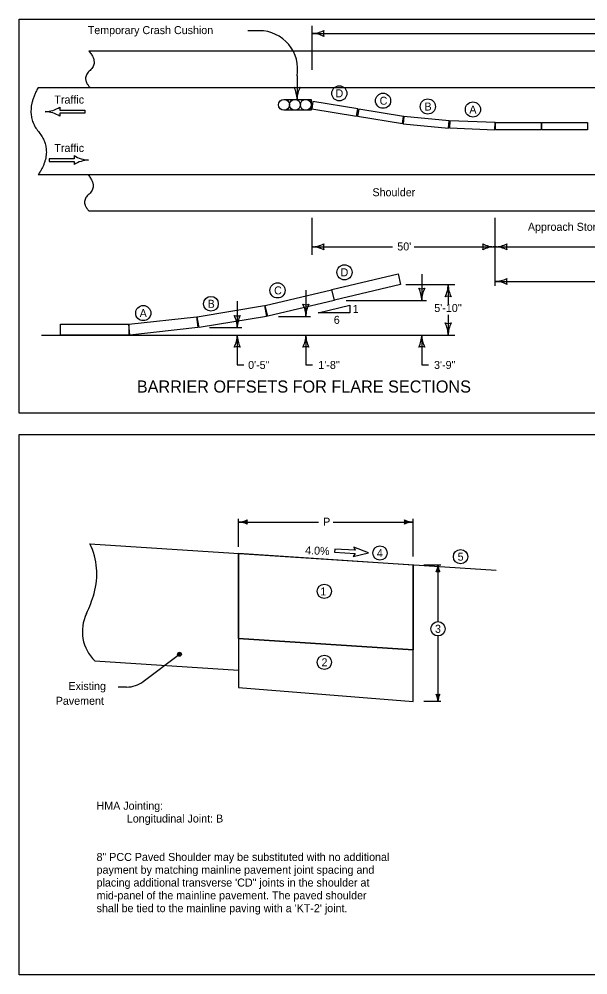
# Model space of a CAD drawing. Extents: x 8045 to 81668, y 6217 to 16762.
# Drawn here: x 13482 to 14421, y 10929 to 12506 of the extents above; entities that cross this region are included whole.
import ezdxf

# ---------------------------------------------------------------- set-up
doc = ezdxf.new("R2010")
doc.units = 0
doc.layers.add('dsnStdLineWork', color=7, linetype='Continuous')

msp = doc.modelspace()

# ---------------------------------------------------------------- linework, layer by layer
at = {"layer": 'dsnStdLineWork'}
for p, q in [((13482.4, 12505.5), (16587.4, 12505.5)), ((13482.4, 11855.5), (13482.4, 12505.5)), ((13965.3, 12494.7), (13965.3, 12422.1)), ((13878.8, 12486.4), (13860.1, 12486.4)), ((13965.3, 12481.9), (14898.2, 12481.9)), ((13597.7, 12453), (14726.2, 12453)), ((13941.1, 12411.7), (13941.1, 12373.1)), ((13514.1, 12393), (14756.2, 12393)), ((13919.5, 12373.1), (13964.5, 12373.1)), ((13964.5, 12373.1), (13964.5, 12355.1)), ((13525.6, 12352.8), (13525.6, 12352.8)), ((13549.5, 12360.3), (13549.5, 12355.1)), ((13549.5, 12355.1), (13590.8, 12355.1)), ((13590.8, 12350.6), (13549.5, 12350.6)), ((13549.5, 12350.6), (13549.5, 12345.3)), ((13590.8, 12355.1), (13590.8, 12350.6)), ((13964.5, 12355.1), (13919.5, 12355.1)), ((13963.3, 12360.8), (13964.6, 12360.5)), ((13965, 12357.1), (13965, 12357.1)), ((13573.1, 12275.2), (13531.9, 12275.2)), ((13531.9, 12275.2), (13531.9, 12270.7)), ((13531.9, 12270.7), (13573.1, 12270.7)), ((13573.1, 12280.5), (13573.1, 12275.2)), ((13573.1, 12270.7), (13573.1, 12265.5)), ((13597.1, 12273), (13597.1, 12273)), ((13514.1, 12249), (14756.2, 12249)), ((13597.7, 12189), (14726.2, 12189)), ((13965.3, 12177.7), (13965.3, 12116.5)), ((14267.5, 12177.7), (14267.5, 12065.3)), ((13965.3, 12129.9), (14098.8, 12129.9)), ((14134.1, 12129.9), (14267.5, 12129.9)), ((14267.5, 12129.9), (14493.6, 12129.9)), ((14146.8, 12085), (14146.8, 12041.6)), ((14120.8, 12067.5), (14201.2, 12067.5)), ((14190.4, 12067.5), (14190.4, 12034.1)), ((14267.5, 12072.8), (14858.3, 12072.8)), ((13955.6, 12058.6), (13955.6, 12015.1)), ((13842.4, 12040.1), (13842.4, 11996.6)), ((13975.7, 12021.2), (14028.3, 12033.6)), ((14021.9, 12041.6), (14154.5, 12041.6)), ((14028.3, 12033.6), (14028.3, 12021.2)), ((13910.6, 12015.1), (13963.4, 12015.1)), ((14028.3, 12021.2), (13975.7, 12021.2)), ((14190.4, 12017.7), (14190.4, 11984.3)), ((13519.4, 11984.3), (14201.2, 11984.3)), ((13796.4, 11996.6), (13850.2, 11996.6)), ((13842.4, 11984.3), (13842.4, 11957.3)), ((13955.6, 11984.3), (13955.6, 11935)), ((14146.8, 11984.3), (14146.8, 11935)), ((13842.4, 11957.3), (13842.4, 11935)), ((13842.4, 11935), (13853.5, 11935)), ((13955.6, 11935), (13966.8, 11935)), ((14146.8, 11935), (14157.9, 11935)), ((16587.4, 11855.5), (13482.4, 11855.5)), ((13844.4, 11635.1), (13844.4, 11681.4)), ((13844.4, 11675.8), (13858.3, 11675.8)), ((13844.4, 11675.8), (13976.7, 11675.8)), ((14000.6, 11675.8), (14132.9, 11675.8)), ((14132.9, 11675.8), (14119.1, 11675.8)), ((14132.9, 11619), (14132.9, 11681.4)), ((13599, 11640.1), (14269.4, 11596.7)), ((14150.2, 11605.5), (14178.2, 11605.5)), ((14173.6, 11605.5), (14173.6, 11594.1)), ((14173.6, 11605.5), (14173.6, 11511.5)), ((13844.4, 11483.8), (14132.9, 11465.1)), ((14173.6, 11488), (14173.6, 11379.9)), ((13687.3, 11413), (13747.3, 11457.9)), ((13607.2, 11446.7), (13844.4, 11431.4)), ((13659.8, 11403.6), (13645.8, 11403.6)), ((14173.6, 11379.9), (14173.6, 11391.4)), ((14178.2, 11379.9), (14150.2, 11379.9))]:
    msp.add_line(p, q, dxfattribs=at)
for points in [[(14041.3, 12357.5), (13967.3, 12369.6), (13965.3, 12357.8), (14039.4, 12345.6)], [(14116.8, 12345.1), (14042.8, 12357.2), (14040.8, 12345.4), (14114.9, 12333.3)], [(14192.2, 12337.9), (14117.5, 12345), (14116.4, 12333), (14191.1, 12325.9)], [(14268, 12335), (14193, 12337.9), (14192.6, 12326), (14267.5, 12323)], [(14268.7, 12335), (14343.7, 12335), (14343.7, 12323), (14268.7, 12323)], [(14345.2, 12335), (14420.2, 12335), (14420.2, 12323), (14345.2, 12323)], [(13998.4, 12059.2), (14107.9, 12085.1), (14112, 12067.6), (14002.6, 12041.7)], [(13888.6, 12033.2), (13998.1, 12059.1), (14002.2, 12041.6), (13892.7, 12015.7)], [(13776.5, 12014.5), (13887.5, 12032.9), (13890.5, 12015.1), (13779.5, 11996.7)], [(13550.9, 12002.4), (13663.4, 12002.3), (13663.4, 11984.3), (13550.9, 11984.4)], [(13663.4, 12002.1), (13775.3, 12014.5), (13777.2, 11996.6), (13665.4, 11984.3)], [(13482.4, 11820.1), (15033.1, 11820.1), (15033.1, 10928.8), (13482.4, 10928.8)], [(13844.4, 11624.4), (14132.9, 11605.5), (14132.9, 11465.1), (13844.4, 11483.8)], [(14033.7, 11619.1), (14058.7, 11625.3), (14034.6, 11634.3), (14037.2, 11629.2), (14003.4, 11631.3), (14003, 11626.2), (14036.9, 11624)]]:
    msp.add_lwpolyline(points, close=True, dxfattribs=at)
for points in [[(13858, 11673.2), (13857.5, 11675.8), (13858, 11678.4), (13854.9, 11676.9), (13850, 11675.8), (13855.3, 11674.5), (13857.6, 11673.5), (13857, 11675.8), (13857.2, 11677.4), (13855.2, 11676.5), (13852.5, 11675.8), (13855.4, 11674.9), (13856.9, 11674.4), (13856.6, 11676.6), (13854.6, 11675.8), (13856.2, 11675.3), (13856.2, 11676), (13855.4, 11675.8)], [(14119.4, 11678.3), (14119.9, 11675.8), (14119.3, 11673.2), (14122.4, 11674.6), (14127.4, 11675.8), (14122.1, 11677), (14119.8, 11678), (14120.4, 11675.8), (14120.1, 11674.1), (14122.2, 11675.1), (14124.9, 11675.8), (14122, 11676.6), (14120.5, 11677.1), (14120.8, 11674.9), (14122.8, 11675.8), (14121.2, 11676.3), (14121.2, 11675.5), (14121.9, 11675.7)], [(13844.4, 11624.4), (13844.4, 11402.6), (14132.9, 11379.9), (14132.9, 11605.5)], [(14171.5, 11594.3), (14173.6, 11594.7), (14175.7, 11594.3), (14174.5, 11596.8), (14173.6, 11600.9), (14172.6, 11596.5), (14171.7, 11594.7), (14173.6, 11595.1), (14175, 11595), (14174.2, 11596.6), (14173.6, 11598.9), (14172.9, 11596.5), (14172.5, 11595.2), (14174.3, 11595.5), (14173.6, 11597.1), (14173.2, 11595.8), (14173.8, 11595.8), (14173.6, 11596.4)], [(13749.3, 11459.6), (13748.2, 11460), (13746.7, 11460.8), (13745.3, 11459.8), (13744.4, 11458.6), (13744.2, 11456.9), (13745.4, 11455.9), (13746.7, 11454.9), (13748.2, 11455.3), (13749.3, 11456.1), (13749.9, 11458.1), (13749.2, 11459.1), (13747.7, 11460), (13746, 11460.2), (13744.9, 11459), (13744.8, 11457.4), (13745.7, 11456.2), (13747.1, 11455.3), (13748, 11455.8), (13749, 11456.3), (13749.4, 11457.9), (13748.5, 11458.7), (13747.4, 11459.5), (13746.1, 11459.7), (13745.5, 11458.3), (13745.7, 11457), (13746.6, 11456), (13747.4, 11456.3), (13748.3, 11456.6), (13748.6, 11457.8), (13748.1, 11458.7), (13747.1, 11459), (13746.3, 11458.4), (13746.1, 11457.5), (13746.6, 11456.7), (13747.2, 11456.6), (13747.8, 11456.8), (13748, 11457.7), (13747.7, 11458.3), (13747, 11458.5), (13746.6, 11458), (13746.7, 11457.4), (13747.2, 11457), (13747.5, 11457.3), (13747.3, 11457.9)], [(14175.7, 11391.1), (14173.6, 11390.7), (14171.4, 11391.1), (14172.7, 11388.6), (14173.6, 11384.5), (14174.6, 11388.9), (14175.4, 11390.8), (14173.6, 11390.3), (14172.2, 11390.5), (14173, 11388.8), (14173.6, 11386.6), (14174.3, 11388.9), (14174.7, 11390.2), (14172.9, 11390), (14173.6, 11388.3), (14174, 11389.6), (14173.4, 11389.6), (14173.6, 11389)]]:
    msp.add_lwpolyline(points, dxfattribs=at)
for centre, radius in [((14010.8, 12383.1), 12.5), ((14083, 12370.9), 12.5), ((13919.5, 12364.1), 9), ((13919.5, 12364.1), 9), ((13937.5, 12364.1), 9), ((13937.5, 12364.1), 9), ((13955.5, 12364.1), 9), ((13955.5, 12364.1), 9), ((14156.8, 12361.3), 12.5), ((14231.3, 12356.4), 12.5), ((14019.3, 12087.8), 12.5), ((13908.9, 12058), 12.5), ((13798.9, 12035.9), 12.2), ((13687.3, 12020.6), 12.5), ((14077.9, 11624.7), 11.8), ((14210.9, 11618.7), 11.8), ((13986, 11561.6), 11.8), ((14173.6, 11499.7), 11.8), ((13747.1, 11457.7), 3.15), ((13986.1, 11444.4), 11.8)]:
    msp.add_circle(centre, radius, dxfattribs=at)
for centre, radius, start, end in [((13878.8, 12423.1), 63.3, 349.6463, 90), ((13965.3, 12524.4), 42.5, 270, 298.0725), ((13965.3, 12439.4), 42.5, 61.9275, 90), ((14001, 12481.9), 16.4, 162.2666, 197.7334), ((13941.1, 12408.7), 16.4, 252.2666, 287.7333), ((13898.6, 12373.1), 42.5, 360, 28.0725), ((13983.6, 12373.1), 42.5, 151.9275, 180), ((13523.6, 12401.2), 48.4, 272.352, 302.382), ((13523.6, 12304.5), 48.4, 57.618, 87.648), ((13599, 12321.3), 48.4, 237.618, 267.648), ((13599, 12224.7), 48.4, 92.352, 122.382), ((13965.3, 12172.4), 42.5, 270, 298.0725), ((13965.3, 12087.4), 42.5, 61.9275, 90), ((14001, 12129.9), 16.4, 162.2666, 197.7334), ((14231.9, 12129.9), 16.4, 342.2666, 17.7333), ((14267.5, 12172.4), 42.5, 241.9275, 270), ((14267.5, 12087.4), 42.5, 90, 118.0725), ((14267.5, 12172.4), 42.5, 270, 298.0725), ((14267.5, 12087.4), 42.5, 61.9275, 90), ((14303.1, 12129.9), 16.4, 162.2666, 197.7334), ((14147.9, 12067.5), 42.5, 331.9275, 360), ((14232.9, 12067.5), 42.5, 180, 208.0725), ((14267.5, 12115.3), 42.5, 270, 298.0725), ((14267.5, 12030.3), 42.5, 61.9275, 90), ((14303.1, 12072.8), 16.4, 162.2666, 197.7334), ((14146.8, 12077.2), 16.4, 252.2666, 287.7333), ((14104.3, 12041.6), 42.5, 360, 28.0725), ((14189.3, 12041.6), 42.5, 151.9275, 180), ((14190.4, 12031.9), 16.4, 72.2666, 107.7334), ((13955.6, 12050.8), 16.4, 252.2666, 287.7333), ((13913.1, 12015.1), 42.5, 360, 28.0725), ((13998.1, 12015.1), 42.5, 151.9275, 180), ((13842.4, 12032.2), 16.4, 252.2666, 287.7333), ((13799.9, 11996.6), 42.5, 360, 28.0725), ((13884.9, 11996.6), 42.5, 151.9275, 180), ((14190.4, 12019.9), 16.4, 252.2666, 287.7333), ((14147.9, 11984.3), 42.5, 360, 28.0725), ((14232.9, 11984.3), 42.5, 151.9275, 180), ((13799.9, 11984.3), 42.5, 331.9275, 360), ((13884.9, 11984.3), 42.5, 180, 208.0725), ((13913.1, 11984.3), 42.5, 331.9275, 360), ((13998.1, 11984.3), 42.5, 180, 208.0725), ((14104.3, 11984.3), 42.5, 331.9275, 360), ((14189.3, 11984.3), 42.5, 180, 208.0725), ((13842.4, 11948.6), 16.4, 72.2666, 107.7334), ((13955.6, 11948.6), 16.4, 72.2666, 107.7334), ((14146.8, 11948.6), 16.4, 72.2666, 107.7334), ((13844.4, 11706.4), 30.6, 270, 298.0725), ((13844.4, 11645.2), 30.6, 61.9275, 90), ((13870.1, 11675.8), 11.8, 162.2666, 197.7334), ((14107.3, 11675.8), 11.8, 342.2666, 17.7334), ((14132.9, 11706.4), 30.6, 241.9275, 270), ((14132.9, 11645.2), 30.6, 90, 118.0725), ((13497.8, 11589.9), 113, 343.6708, 26.3373), ((14148.3, 11605.5), 25.2, 331.9275, 360), ((14198.8, 11605.5), 25.2, 180, 208.0725), ((14173.6, 11584.3), 9.75, 72.2666, 107.7334), ((13393.8, 11620.4), 221.4, 334.4332, 343.6708), ((13655, 11495.4), 68.2, 154.4332, 225.5564), ((13659.8, 11448.6), 45, 270, 307.6187), ((14173.6, 11401.1), 9.75, 252.2666, 287.7334), ((14148.3, 11379.9), 25.2, 360, 28.0725), ((14198.8, 11379.9), 25.2, 151.9275, 180)]:
    msp.add_arc(centre, radius, start, end, dxfattribs=at)
for points in [[(13597.7, 12453), (13613.8, 12433.6), (13584.9, 12408), (13599.3, 12393)], [(13514.1, 12393), (13489.5, 12350.3), (13540.2, 12288.1), (13514.1, 12249)], [(13596.1, 12248.9), (13612.2, 12229.6), (13583.2, 12204), (13597.7, 12189)]]:
    msp.add_open_spline(points, degree=2, dxfattribs=at)

# ---------------------------------------------------------------- texts
for s, height, p in [('Temporary Crash Cushion', 13.2, (13595.7, 12480.8)), ('Traffic', 13.2, (13540.6, 12366.2)), ('D', 13.2, (14004.5, 12376.5)), ('C', 13.2, (14077.3, 12364.3)), ('B', 13.2, (14151.3, 12354.7)), ('A', 13.2, (14225.4, 12349.8)), ('Traffic', 13.2, (13540.6, 12286.4)), ('Shoulder', 13.2, (14065.5, 12213.3)), ("Approach Storage Area (minimum 20')", 13.2, (14322, 12156.3)), ("50'", 13.2, (14106.5, 12123.9)), ('D', 13.2, (14012.9, 12081.2)), ('C', 13.2, (13903.2, 12051.4)), ('B', 13.2, (13793.5, 12029.3)), ('1', 13.2, (14032.9, 12020.9)), ("5'-10''", 13.2, (14167.5, 12022.4)), ('A', 13.2, (13681.4, 12014)), ('6', 13.2, (14001.7, 12002.8)), ("0'-5''", 13.2, (13860.3, 11928.4)), ("1'-8''", 13.2, (13976.2, 11928.4)), ("3'-9''", 13.2, (14167.1, 11928.4)), ('BARRIER OFFSETS FOR FLARE SECTIONS', 20, (13676.7, 11889.4)), ('P', 13.2, (13984.1, 11669.8)), ('4', 13.2, (14072.8, 11618.1)), ('5', 13.2, (14206.1, 11612.1)), ('1', 13.2, (13979.5, 11554.7)), ('3', 13.2, (14168.7, 11493.1)), ('2', 13.2, (13981.4, 11437.8)), ('Existing', 13.2, (13563.9, 11398.7)), ('Pavement', 13.2, (13542.9, 11374.3)), ('HMA Jointing:', 13.2, (13610.2, 11201.2)), ('Longitudinal Joint: B', 13.2, (13660.2, 11180.1)), ('8" PCC Paved Shoulder may be substituted with no additional ', 13.2, (13610.2, 11116.7)), ('payment by matching mainline pavement joint spacing and ', 13.2, (13610.3, 11095.6)), ('placing additional transverse \'CD" joints in the shoulder at ', 13.2, (13610.3, 11074.5)), ('mid-panel of the mainline pavement. The paved shoulder ', 13.2, (13610.3, 11053.4)), ("shall be tied to the mainline paving with a 'KT-2' joint.", 13.2, (13610.3, 11032.2))]:
    msp.add_text(s, height=height, dxfattribs=at).set_placement(p)
msp.add_text('4.0%', height=13.2, rotation=357.4961, dxfattribs=at).set_placement((13954.2, 11622.9))

doc.saveas('drawing.dxf')
